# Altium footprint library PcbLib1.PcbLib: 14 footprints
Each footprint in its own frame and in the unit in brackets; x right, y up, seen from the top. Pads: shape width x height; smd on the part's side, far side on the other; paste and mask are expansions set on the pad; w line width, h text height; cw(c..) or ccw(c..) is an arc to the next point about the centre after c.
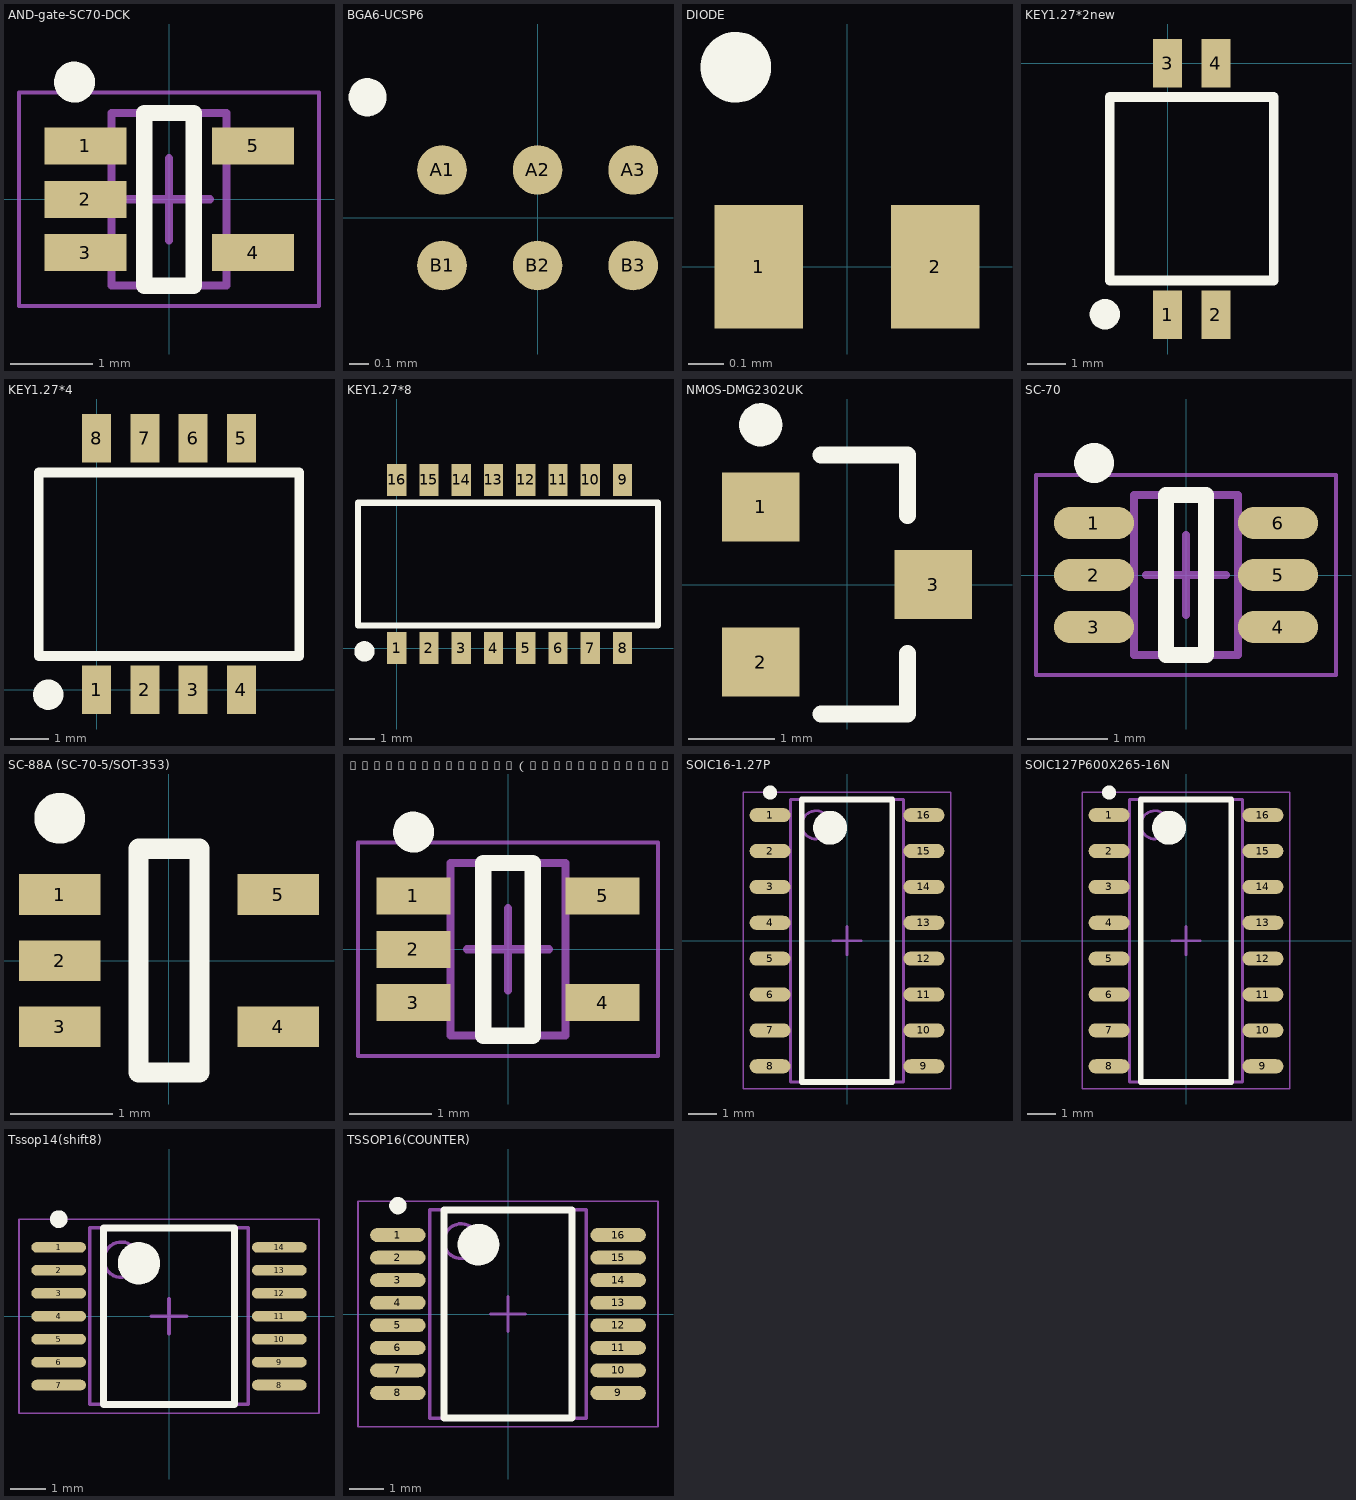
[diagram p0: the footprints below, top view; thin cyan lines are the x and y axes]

## AND-gate-SC70-DCK [mm] "SOT23, 5-Leads, Body 2.10x2.35mm, Pitch 0.65mm, IPC Medium Density"
height 1.1
pads (5):
  rect 1x0.45 smd: 1(-1.016,0.65) 2(-1.016,0) 3(-1.016,-0.65) 4(1.023,-0.65) 5(1.023,0.65)
Top Overlay:
  circle w0.25: c-1.15,1.425 r0.125
  lines w0.2: -0.3,-1.05 0.3,-1.05 0.3,1.05 -0.3,1.05 -0.3,-1.05
Mechanical 13:
  lines w0.1: -0.7,-1.05 -0.7,1.05 0.7,1.05 0.7,-1.05 -0.7,-1.05
Mechanical 15:
  lines w0.05: -1.825,-1.3 -1.825,1.3 1.825,1.3 1.825,-1.3 -1.825,-1.3
  lines w0.1: -0.5,0 0.5,0 ; 0,-0.5 0,0.5
3D body: height 1.1, standoff 0.05, extent -0.7,-1.05 0.7,1.05

## BGA6-UCSP6 [mm] "BGA, 6-Leads, Body 1.57x1.05mmx0.69mm, Pitch 1.00mm"
height 0.69
pads (6):
  round 0.26 smd: A1(-0.5,0.25) A2(0,0.25) A3(0.5,0.25) B1(-0.5,-0.25) B2(0,-0.25) B3(0.5,-0.25)
Top Overlay:
  circle w0.1: c-0.89,0.63 r0.05
3D body: height 0.69, standoff 0.21, extent -0.785,-0.525 0.785,0.525

## DIODE [mm] "DFN, 2-Leads, Body 0.30x0.60mm, Pitch 0.40mm, IPC Medium Density"
height 0.32
pads (2):
  rect 0.25x0.35 smd: 1(-0.25,0) 2(0.25,0)
Top Overlay:
  circle w0.1: c-0.315,0.565 r0.05
3D body: height 0.32, standoff 0.03, extent -0.315,-0.165 0.315,0.165

## KEY1.27*2new [mm]
pads (4):
  rect 0.76x1.27 smd: 1(0,-6.62) 2(1.27,-6.62) 3(0,0) 4(1.27,0)
Top Overlay:
  circle w0.44: c-1.651,-6.604 r0.18
  lines w0.254: -1.524,-5.715 2.794,-5.715 2.794,-0.889 -1.524,-0.889 -1.524,-5.715

## KEY1.27*4 [mm]
pads (8):
  rect 0.76x1.27 smd: 1(0,0) 2(1.27,0) 3(2.54,0) 4(3.81,0) 5(3.81,6.62) 6(2.54,6.62) 7(1.27,6.62) 8(0,6.62)
Top Overlay:
  circle w0.44: c-1.27,-0.127 r0.18
  lines w0.254: -1.524,0.889 -1.524,5.715 5.334,5.715 5.334,0.889 -1.524,0.889

## KEY1.27*8 [mm]
pads (16):
  rect 0.76x1.27 smd: 1(0,0) 2(1.27,0) 3(2.54,0) 4(3.81,0) 5(5.08,0) 6(6.35,0) 7(7.62,0) 8(8.89,0) 9(8.89,6.62) 10(7.62,6.62) 11(6.35,6.62) 12(5.08,6.62) 13(3.81,6.62) 14(2.54,6.62) 15(1.27,6.62) 16(0,6.62)
Top Overlay:
  circle w0.44: c-1.27,-0.127 r0.18
  lines w0.254: -1.524,0.889 -1.524,5.715 10.287,5.715 10.287,0.889 -1.524,0.889

## NMOS-DMG2302UK [mm]
height 1.1
pads (3):
  rect 0.9x0.8 smd: 1(-1,0.9) 2(-1,-0.9) 3(1,0)
Top Overlay:
  circle w0.25: c-1,1.85 r0.125
  lines w0.2: -0.3,-1.5 0.7,-1.5 0.7,-0.8 ; -0.3,1.5 0.7,1.5 0.7,0.8
3D body: height 1.1, standoff 0.01, extent -0.7,-1.5 0.7,1.5

## SC-70 [mm] "SOP, 6-Leads, Body 2.00x1.25mm, Pitch 0.65mm, IPC Medium Density"
height 2.65
pads (6):
  oval 1x0.4 smd: 1(-1.15,0.65) 2(-1.15,0) 3(-1.15,-0.65) 4(1.15,-0.65) 5(1.15,0) 6(1.15,0.65)
Top Overlay:
  circle w0.25: c-1.15,1.4 r0.125
  lines w0.2: -0.25,-1 -0.25,1 0.25,1 0.25,-1 -0.25,-1
Mechanical 13:
  lines w0.1: -0.65,-1 -0.65,1 0.65,1 0.65,-1 -0.65,-1
Mechanical 15:
  lines w0.05: -1.875,-1.25 -1.875,1.25 1.875,1.25 1.875,-1.25 -1.875,-1.25
  lines w0.1: -0.5,0 0.5,0 ; 0,-0.5 0,0.5
3D body: height 2.65, standoff 0.1, extent -0.65,-1 0.65,1

## SC-88A (SC-70-5/SOT-353) [mm] "SOT23, 5-Leads, Body 2.00x2.10mm, Pitch 0.65mm, IPC Medium Density"
height 1.1
pads (5):
  rect 0.8x0.4 smd: 1(-1.075,0.65) 2(-1.075,0) 3(-1.075,-0.65) 4(1.075,-0.65) 5(1.075,0.65)
Top Overlay:
  circle w0.25: c-1.075,1.4 r0.125
  lines w0.2: -0.3,-1.1 0.3,-1.1 0.3,1.1 -0.3,1.1 -0.3,-1.1
3D body: height 1.1, standoff 0.1, extent -0.675,-1.1 0.675,1.1

## SN74AUP1G32DCK（OR-gate-SC70-DCK） [mm] "SOT23, 5-Leads, Body 2.10x2.35mm, Pitch 0.65mm, IPC Medium Density"
height 1.1
pads (5):
  rect 0.9x0.45 smd: 1(-1.15,0.65) 2(-1.15,0) 3(-1.15,-0.65) 4(1.15,-0.65) 5(1.15,0.65)
Top Overlay:
  circle w0.25: c-1.15,1.425 r0.125
  lines w0.2: -0.3,-1.05 0.3,-1.05 0.3,1.05 -0.3,1.05 -0.3,-1.05
Mechanical 13:
  lines w0.1: -0.7,-1.05 -0.7,1.05 0.7,1.05 0.7,-1.05 -0.7,-1.05
Mechanical 15:
  lines w0.05: -1.825,-1.3 -1.825,1.3 1.825,1.3 1.825,-1.3 -1.825,-1.3
  lines w0.1: -0.5,0 0.5,0 ; 0,-0.5 0,0.5
3D body: height 1.1, standoff 0.05, extent -0.7,-1.05 0.7,1.05

## SOIC16-1.27P [mm] "SOIC, 16-Leads, Body 10.00x4.00mm, Pitch 1.27mm, IPC Medium Density"
height 2.65
pads (16):
  oval 1.45x0.5 smd: 1(-2.725,4.445) 2(-2.725,3.175) 3(-2.725,1.905) 4(-2.725,0.635) 5(-2.725,-0.635) 6(-2.725,-1.905) 7(-2.725,-3.175) 8(-2.725,-4.445) 9(2.725,-4.445) 10(2.725,-3.175) 11(2.725,-1.905) 12(2.725,-0.635) 13(2.725,0.635) 14(2.725,1.905) 15(2.725,3.175) 16(2.725,4.445)
Top Overlay:
  circle w0.25: c-2.725,5.245 r0.125
  circle w0.6: c-0.6,4 r0.3
  lines w0.2: -1.6,-5 -1.6,5 1.6,5 1.6,-5 -1.6,-5
Mechanical 13:
  circle w0.1: c-1.1,4.1 r0.5
  lines w0.1: -2,-5 -2,5 2,5 2,-5 -2,-5
Mechanical 15:
  lines w0.05: -3.675,-5.25 -3.675,5.25 3.675,5.25 3.675,-5.25 -3.675,-5.25
  lines w0.1: -0.5,0 0.5,0 ; 0,-0.5 0,0.5
3D body: height 2.65, standoff 0.1, extent -2,-5 2,5

## SOIC127P600X265-16N [mm] "SOIC, 16-Leads, Body 10.00x4.00mm, Pitch 1.27mm, IPC Medium Density"
height 2.65
pads (16):
  oval 1.45x0.5 smd: 1(-2.725,4.445) 2(-2.725,3.175) 3(-2.725,1.905) 4(-2.725,0.635) 5(-2.725,-0.635) 6(-2.725,-1.905) 7(-2.725,-3.175) 8(-2.725,-4.445) 9(2.725,-4.445) 10(2.725,-3.175) 11(2.725,-1.905) 12(2.725,-0.635) 13(2.725,0.635) 14(2.725,1.905) 15(2.725,3.175) 16(2.725,4.445)
Top Overlay:
  circle w0.6: c-0.6,4 r0.3
  circle w0.25: c-2.725,5.245 r0.125
  lines w0.2: -1.6,-5 1.6,-5 1.6,5 -1.6,5 -1.6,-5
Mechanical 13:
  circle w0.1: c-1.1,4.1 r0.5
  lines w0.1: -2,-5 2,-5 2,5 -2,5 -2,-5
Mechanical 15:
  lines w0.05: -3.675,-5.25 3.675,-5.25 3.675,5.25 -3.675,5.25 -3.675,-5.25
  lines w0.1: -0.5,0 0.5,0 ; 0,-0.5 0,0.5
3D body: height 2.65, standoff 0.1, extent -2,-5 2,5

## Tssop14(shift8) [mm] "SOP, 14-Leads, Body 5.00x4.50mm, Pitch 0.65mm, IPC Medium Density"
height 2.65
pads (14):
  oval 1.55x0.3 smd: 1(-3.125,1.95) 2(-3.125,1.3) 3(-3.125,0.65) 4(-3.125,0) 5(-3.125,-0.65) 6(-3.125,-1.3) 7(-3.125,-1.95) 8(3.125,-1.95) 9(3.125,-1.3) 10(3.125,-0.65) 11(3.125,0) 12(3.125,0.65) 13(3.125,1.3) 14(3.125,1.95)
Top Overlay:
  circle w0.25: c-3.125,2.75 r0.125
  circle w0.6: c-0.85,1.5 r0.3
  lines w0.2: -1.85,-2.5 -1.85,2.5 1.85,2.5 1.85,-2.5 -1.85,-2.5
Mechanical 13:
  circle w0.1: c-1.35,1.6 r0.5
  lines w0.1: -2.25,-2.5 -2.25,2.5 2.25,2.5 2.25,-2.5 -2.25,-2.5
Mechanical 15:
  lines w0.05: -4.25,-2.75 -4.25,2.75 4.25,2.75 4.25,-2.75 -4.25,-2.75
  lines w0.1: -0.5,0 0.5,0 ; 0,-0.5 0,0.5
3D body: height 2.65, standoff 0.1, extent -2.25,-2.5 2.25,2.5

## TSSOP16(COUNTER) [mm] "SOP, 16-Leads, Body 6.00x4.50mm, Pitch 0.65mm, IPC Medium Density"
height 2.65
pads (16):
  oval 1.6x0.4 smd: 1(-3.175,2.275) 2(-3.175,1.625) 3(-3.175,0.975) 4(-3.175,0.325) 5(-3.175,-0.325) 6(-3.175,-0.975) 7(-3.175,-1.625) 8(-3.175,-2.275) 9(3.175,-2.275) 10(3.175,-1.625) 11(3.175,-0.975) 12(3.175,-0.325) 13(3.175,0.325) 14(3.175,0.975) 15(3.175,1.625) 16(3.175,2.275)
Top Overlay:
  circle w0.6: c-0.85,2 r0.3
  circle w0.25: c-3.175,3.125 r0.125
  lines w0.2: -1.85,-3 1.85,-3 1.85,3 -1.85,3 -1.85,-3
Mechanical 13:
  circle w0.1: c-1.35,2.1 r0.5
  lines w0.1: -2.25,-3 2.25,-3 2.25,3 -2.25,3 -2.25,-3
Mechanical 15:
  lines w0.05: -4.325,-3.25 4.325,-3.25 4.325,3.25 -4.325,3.25 -4.325,-3.25
  lines w0.1: -0.5,0 0.5,0 ; 0,-0.5 0,0.5
3D body: height 2.65, standoff 0.1, extent -2.25,-3 2.25,3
